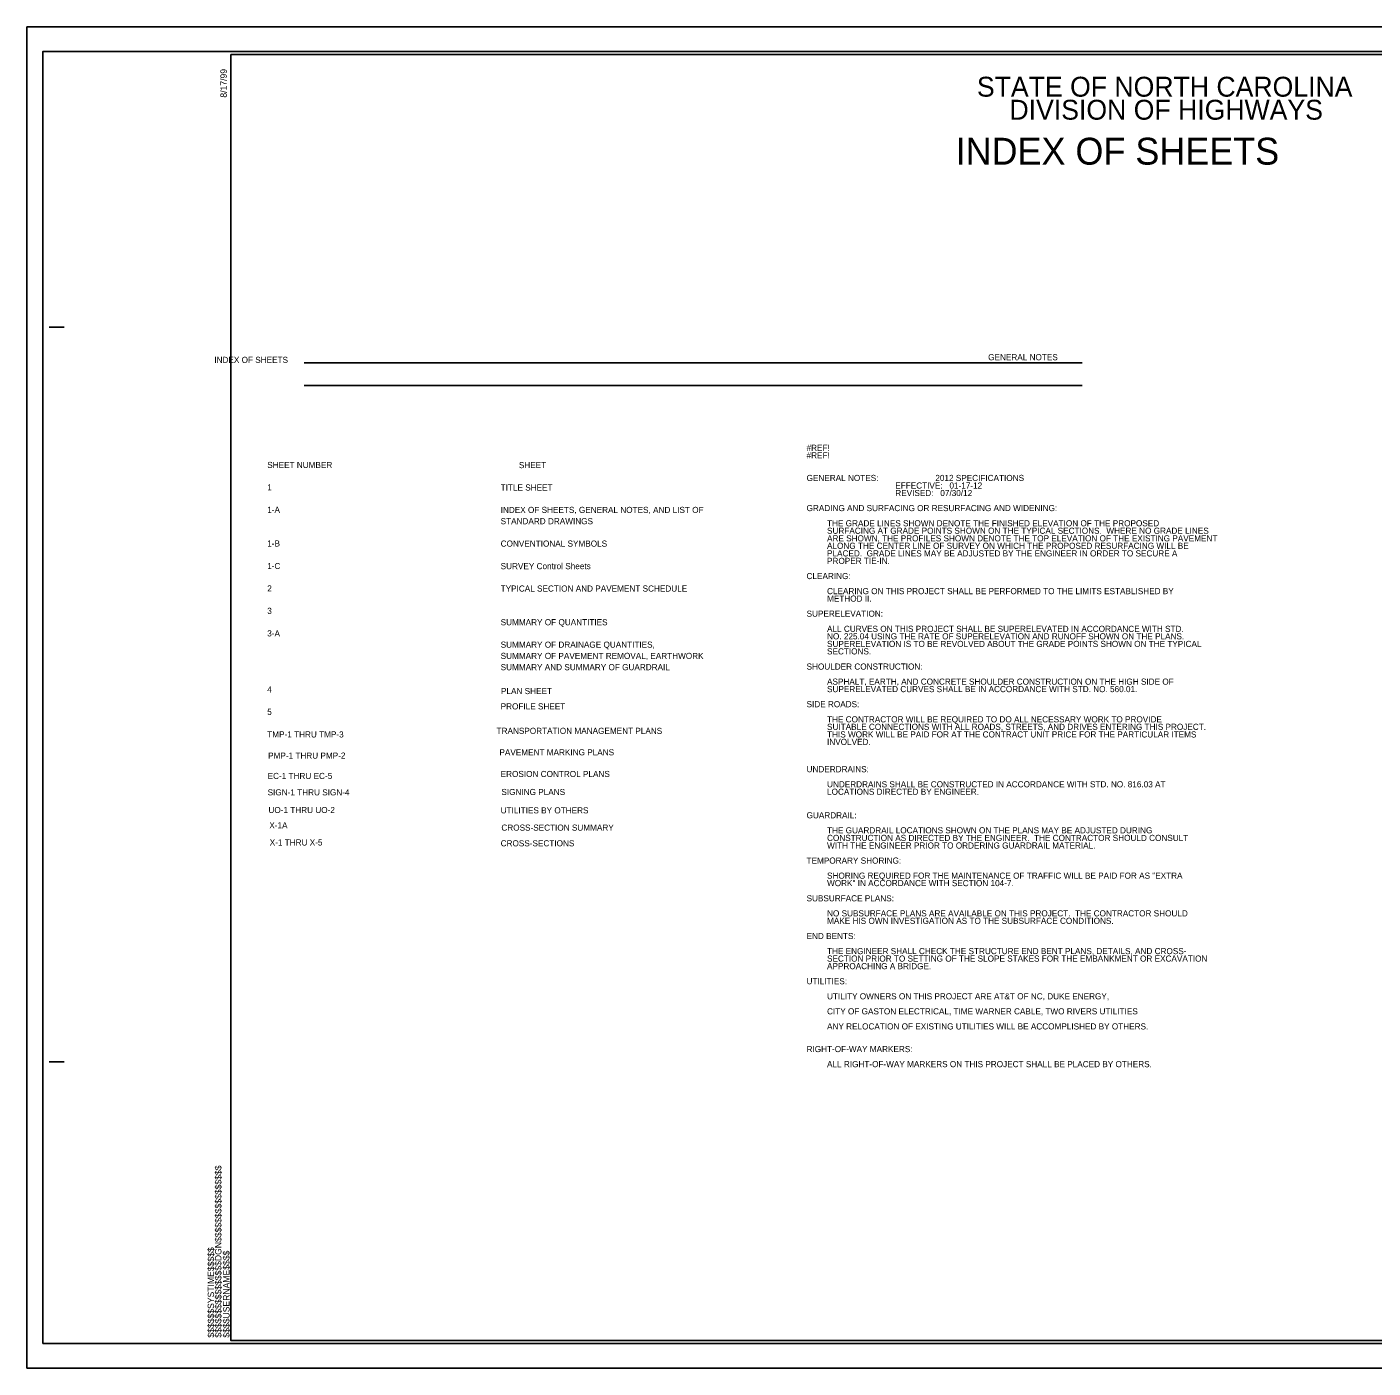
# Model space of a CAD drawing. Extents: x 573855 to 575539, y -53293 to -50956.
# Drawn here: x 573856 to 574955, y -52051 to -50956 of the extents above; entities that cross this region are included whole.
import ezdxf

# ---------------------------------------------------------------- set-up
doc = ezdxf.new("R2010")
doc.units = 0
for name, color, linetype in [('Default', 7, 'Continuous'), ('Scratch_Level_1', 7, 'Continuous'), ('Sheet Cutting Line CELL', 7, 'Continuous'), ('Sheet Plan CELL', 7, 'Continuous'), ('Sheet Plot Border Inside CELL', 7, 'Continuous'), ('Sheet Plot Border Outside CELL', 7, 'Continuous'), ('Sheet Summary CELL', 7, 'Continuous')]:
    doc.layers.add(name, color=color, linetype=linetype)

msp = doc.modelspace()

# ---------------------------------------------------------------- linework, layer by layer
at = {"layer": 'Scratch_Level_1'}
for p, q in [((574082, -51230), (574717.3, -51230)), ((574082.1, -51248.4), (574717.4, -51248.4))]:
    msp.add_line(p, q, dxfattribs=at)
at = {"layer": 'Sheet Cutting Line CELL'}
for p, q in [((575539.2, -50955.8), (573855.7, -50955.8)), ((573855.7, -50955.8), (573855.7, -52050.8)), ((573855.7, -52050.8), (575539.2, -52050.8))]:
    msp.add_line(p, q, dxfattribs=at)
at = {"layer": 'Sheet Plan CELL'}
for p, q in [((574022.2, -50978.3), (574022.2, -50978.3)), ((573873.7, -51200.8), (573886.2, -51200.8)), ((573873.7, -51800.8), (573886.2, -51800.8)), ((574022.2, -52028.3), (574022.2, -52028.3))]:
    msp.add_line(p, q, dxfattribs=at)
msp.add_lwpolyline([(575522.2, -50978.3), (574022.2, -50978.3), (574022.2, -52028.3), (575522.2, -52028.3)], close=True, dxfattribs=at)
at = {"layer": 'Sheet Plot Border Inside CELL'}
msp.add_lwpolyline([(573868.7, -52030.8), (575534.7, -52030.8), (575534.7, -50975.8), (573868.7, -50975.8)], close=True, dxfattribs=at)
at = {"layer": 'Sheet Plot Border Outside CELL'}
msp.add_lwpolyline([(573855.7, -52050.8), (575539.2, -52050.8), (575539.2, -50955.8), (573855.7, -50955.8)], close=True, dxfattribs=at)
at = {"layer": 'Sheet Summary CELL'}
msp.add_line((574763.6, -51057.3), (574763.6, -51057.3), dxfattribs=at)

# ---------------------------------------------------------------- texts
at = {"layer": 'Default'}
for s, p in [('#REF!', (574492.3, -51301.9)), ('#REF!', (574492.3, -51308)), ('GENERAL NOTES:                         2012 SPECIFICATIONS', (574492.3, -51326.5)), ('                                       EFFECTIVE:   01-17-12', (574492.3, -51332.7)), ('                                       REVISED:   07/30/12', (574492.3, -51338.8)), ('GRADING AND SURFACING OR RESURFACING AND WIDENING:  ', (574492.3, -51351.1)), ('         THE GRADE LINES SHOWN DENOTE THE FINISHED ELEVATION OF THE PROPOSED ', (574492.3, -51363.5)), ('         SURFACING AT GRADE POINTS SHOWN ON THE TYPICAL SECTIONS.  WHERE NO GRADE LINES ', (574492.3, -51369.6)), ('         ARE SHOWN, THE PROFILES SHOWN DENOTE THE TOP ELEVATION OF THE EXISTING PAVEMENT ', (574492.3, -51375.8)), ('         ALONG THE CENTER LINE OF SURVEY ON WHICH THE PROPOSED RESURFACING WILL BE ', (574492.3, -51381.9)), ('         PLACED.  GRADE LINES MAY BE ADJUSTED BY THE ENGINEER IN ORDER TO SECURE A ', (574492.3, -51388.1)), ('         PROPER TIE-IN.  ', (574492.3, -51394.2)), ('CLEARING:  ', (574492.3, -51406.6)), ('         CLEARING ON THIS PROJECT SHALL BE PERFORMED TO THE LIMITS ESTABLISHED BY ', (574492.3, -51418.9)), ('         METHOD II.', (574492.3, -51425)), ('SUPERELEVATION:  ', (574492.3, -51437.3)), ('         ALL CURVES ON THIS PROJECT SHALL BE SUPERELEVATED IN ACCORDANCE WITH STD. ', (574492.3, -51449.7)), ('         NO. 225.04 USING THE RATE OF SUPERELEVATION AND RUNOFF SHOWN ON THE PLANS.', (574492.3, -51455.8)), ('         SUPERELEVATION IS TO BE REVOLVED ABOUT THE GRADE POINTS SHOWN ON THE TYPICAL ', (574492.3, -51462)), ('         SECTIONS.  ', (574492.3, -51468.1)), ('SHOULDER CONSTRUCTION:  ', (574492.3, -51480.5)), ('         ASPHALT, EARTH, AND CONCRETE SHOULDER CONSTRUCTION ON THE HIGH SIDE OF', (574492.3, -51492.8)), ('         SUPERELEVATED CURVES SHALL BE IN ACCORDANCE WITH STD. NO. 560.01.', (574492.3, -51498.9)), ('SIDE ROADS:  ', (574492.3, -51511.2)), ('         THE CONTRACTOR WILL BE REQUIRED TO DO ALL NECESSARY WORK TO PROVIDE ', (574492.3, -51523.6)), ('         THIS WORK WILL BE PAID FOR AT THE CONTRACT UNIT PRICE FOR THE PARTICULAR ITEMS ', (574492.3, -51535.9)), ('         SUITABLE CONNECTIONS WITH ALL ROADS, STREETS, AND DRIVES ENTERING THIS PROJECT.  ', (574492.3, -51529.7)), ('         INVOLVED.  ', (574492.3, -51542)), ('UNDERDRAINS:  ', (574492.3, -51564.3)), ('         UNDERDRAINS SHALL BE CONSTRUCTED IN ACCORDANCE WITH STD. NO. 816.03 AT', (574492.3, -51576.6)), ('         LOCATIONS DIRECTED BY ENGINEER.', (574492.3, -51582.7)), ('GUARDRAIL:  ', (574492.3, -51601.9)), ('         THE GUARDRAIL LOCATIONS SHOWN ON THE PLANS MAY BE ADJUSTED DURING ', (574492.3, -51614.2)), ('         CONSTRUCTION AS DIRECTED BY THE ENGINEER.  THE CONTRACTOR SHOULD CONSULT', (574492.3, -51620.4)), ('         WITH THE ENGINEER PRIOR TO ORDERING GUARDRAIL MATERIAL.', (574492.3, -51626.6)), ('TEMPORARY SHORING:  ', (574492.3, -51638.9)), ('         WORK" IN ACCORDANCE WITH SECTION 104-7.  ', (574492.3, -51657.3)), ('         SHORING REQUIRED FOR THE MAINTENANCE OF TRAFFIC WILL BE PAID FOR AS "EXTRA ', (574492.3, -51651.2)), ('SUBSURFACE PLANS:  ', (574492.3, -51669.7)), ('         NO SUBSURFACE PLANS ARE AVAILABLE ON THIS PROJECT.  THE CONTRACTOR SHOULD ', (574492.3, -51682)), ('         MAKE HIS OWN INVESTIGATION AS TO THE SUBSURFACE CONDITIONS.  ', (574492.3, -51688.1)), ('END BENTS:  ', (574492.3, -51700.5)), ('         THE ENGINEER SHALL CHECK THE STRUCTURE END BENT PLANS, DETAILS, AND CROSS-', (574492.3, -51712.8)), ('         SECTION PRIOR TO SETTING OF THE SLOPE STAKES FOR THE EMBANKMENT OR EXCAVATION ', (574492.3, -51718.9)), ('         APPROACHING A BRIDGE.  ', (574492.3, -51725.1)), ('UTILITIES:  ', (574492.3, -51737.4)), ('         UTILITY OWNERS ON THIS PROJECT ARE AT&T OF NC, DUKE ENERGY,', (574492.3, -51749.7)), ('         CITY OF GASTON ELECTRICAL, TIME WARNER CABLE, TWO RIVERS UTILITIES', (574492.3, -51762)), ('         ANY RELOCATION OF EXISTING UTILITIES WILL BE ACCOMPLISHED BY OTHERS.  ', (574492.3, -51774.3)), ('RIGHT-OF-WAY MARKERS:  ', (574492.3, -51792.8)), ('         ALL RIGHT-OF-WAY MARKERS ON THIS PROJECT SHALL BE PLACED BY OTHERS.  ', (574492.3, -51805.1))]:
    msp.add_text(s, height=5, dxfattribs=at).set_placement(p)
at = {"layer": 'Sheet Plan CELL'}
for s, p in [('8/17/99', (574018.9, -51013.5)), ('$$$$$$$$$$$$$$$$DGN$$$$$$$$$$$$$$$$', (574014.5, -52025.9)), ('$$$$$$SYSTIME$$$$$', (574008.5, -52025.9)), ('$$$$USERNAME$$$$', (574021.1, -52025.9))]:
    msp.add_text(s, height=5.25, rotation=90, dxfattribs=at).set_placement(p)
at = {"layer": 'Sheet Summary CELL'}
for s, height, p in [('STATE OF NORTH CAROLINA', 16.25, (574631.4, -51012.7)), ('DIVISION OF HIGHWAYS', 16.25, (574658, -51031.5)), ('INDEX OF SHEETS', 21.95, (574614, -51068.2)), ('GENERAL NOTES', 5, (574640.6, -51227.9)), ('                        INDEX OF SHEETS ', 5, (573964.1, -51230.1)), ('SHEET NUMBER   ', 5, (574051.9, -51315.9)), ('        SHEET   ', 5, (574242.5, -51316)), ('1 ', 5, (574051.9, -51334.2)), ('TITLE SHEET', 5, (574242.5, -51334.3)), ('1-A  ', 5, (574051.9, -51352.5)), ('INDEX OF SHEETS, GENERAL NOTES, AND LIST OF ', 5, (574242.5, -51352.6)), ('STANDARD DRAWINGS', 5, (574242.5, -51361.8)), ('1-B  ', 5, (574051.9, -51380)), ('CONVENTIONAL SYMBOLS ', 5, (574242.5, -51380.1)), ('1-C', 5, (574051.9, -51398.4)), ('SURVEY Control Sheets', 5, (574242.5, -51398.5)), ('2  ', 5, (574051.9, -51416.7)), ('TYPICAL SECTION AND PAVEMENT SCHEDULE', 5, (574242.5, -51416.8)), ('3  ', 5, (574051.9, -51435)), ('SUMMARY OF QUANTITIES ', 5, (574242.5, -51444.3)), ('3-A  ', 5, (574051.9, -51453.4)), ('SUMMARY OF DRAINAGE QUANTITIES, ', 5, (574242.5, -51462.6)), ('SUMMARY OF PAVEMENT REMOVAL, EARTHWORK ', 5, (574242.5, -51471.8)), ('SUMMARY AND SUMMARY OF GUARDRAIL', 5, (574242.5, -51481)), ('4', 5, (574051.9, -51499.2)), ('PLAN SHEET', 5, (574242.8, -51500.5)), ('PROFILE SHEET  ', 5, (574242.5, -51513)), ('5  ', 5, (574051.9, -51517.5)), ('TMP-1 THRU TMP-3', 5, (574051.9, -51535.9)), ('TRANSPORTATION MANAGEMENT PLANS', 5, (574239.2, -51533)), ('PMP-1 THRU PMP-2', 5, (574052.6, -51553.2)), ('PAVEMENT MARKING PLANS', 5, (574241.5, -51550.5)), ('EC-1 THRU EC-5', 5, (574052.2, -51569.8)), ('EROSION CONTROL PLANS', 5, (574242.5, -51568.2)), ('SIGN-1 THRU SIGN-4', 5, (574052.2, -51583.2)), ('SIGNING PLANS', 5, (574243.1, -51582.9)), ('UO-1 THRU UO-2', 5, (574052.9, -51597.6)), ('UTILITIES BY OTHERS', 5, (574242.5, -51597.9)), ('X-1A', 5, (574053.6, -51610.1)), ('CROSS-SECTION SUMMARY', 5, (574243.1, -51612)), ('X-1 THRU X-5', 5, (574053.9, -51624.1)), ('CROSS-SECTIONS', 5, (574242.5, -51624.8))]:
    msp.add_text(s, height=height, rotation=360, dxfattribs=at).set_placement(p)

doc.saveas('drawing.dxf')
